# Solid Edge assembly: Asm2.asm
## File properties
Author: Robert a Rhodes jr
Template: Normal.asm
Last saved by: Cadcim
Revision: 10
Application: Solid Edge
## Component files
Part1.par
Part2.par
Part3.par
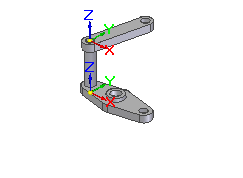
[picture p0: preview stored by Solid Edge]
